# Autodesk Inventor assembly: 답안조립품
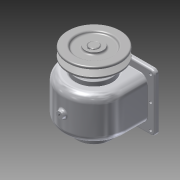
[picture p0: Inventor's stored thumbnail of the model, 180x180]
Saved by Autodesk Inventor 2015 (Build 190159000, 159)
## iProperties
Created: 2015-09
Part Number: 답안조립품
Document SubType Name: Assembly
Designer: Administrator
Author: Administrator
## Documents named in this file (14)
- C:\Users\Administrator\Desktop\450908V1017\답안조립품.iam
- C:\Users\Administrator\Desktop\450908V1017\본체.ipt
- C:\Users\Administrator\Desktop\450908V1017\축.ipt
- C:\Users\Administrator\Desktop\450908V1017\키 - 5 x 5 x 18.ipt
- C:\Users\Administrator\Desktop\450908V1017\베어링 6203.ipt
- C:\Users\Administrator\Desktop\450908V1017\뒤커버.ipt
- C:\Users\Administrator\Desktop\450908V1017\스퍼기어.ipt
- C:\Users\Administrator\Desktop\450908V1017\V-벨트풀리.ipt
- C:\Users\Administrator\Desktop\450908V1017\앞커버.ipt
- C:\Users\Administrator\Desktop\450908V1017\키 - 6 x 6 x 22.ipt
- C:\Users\Administrator\Desktop\450908V1017\오일 실 17 32 8.ipt
- C:\Users\Administrator\Desktop\450908V1017\멈춤나사 - M4x10.ipt
- C:\Users\Administrator\Desktop\450908V1017\볼트 M3 x 8.ipt
- C:\Users\Administrator\Desktop\450908V1017\볼트 M3 x 10.ipt
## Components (9 placed, 3 different names)
1. V-벨트풀리:1
2. ISO 4762 M3 x 8:1
3. ISO 4762 M3 x 8:2
4. ISO 4762 M3 x 8:3
5. ISO 4762 M3 x 8:4
6. ISO 4762 M3 x 10:1
7. ISO 4762 M3 x 10:2
8. ISO 4762 M3 x 10:3
9. ISO 4762 M3 x 10:4
